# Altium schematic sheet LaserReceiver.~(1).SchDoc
size A
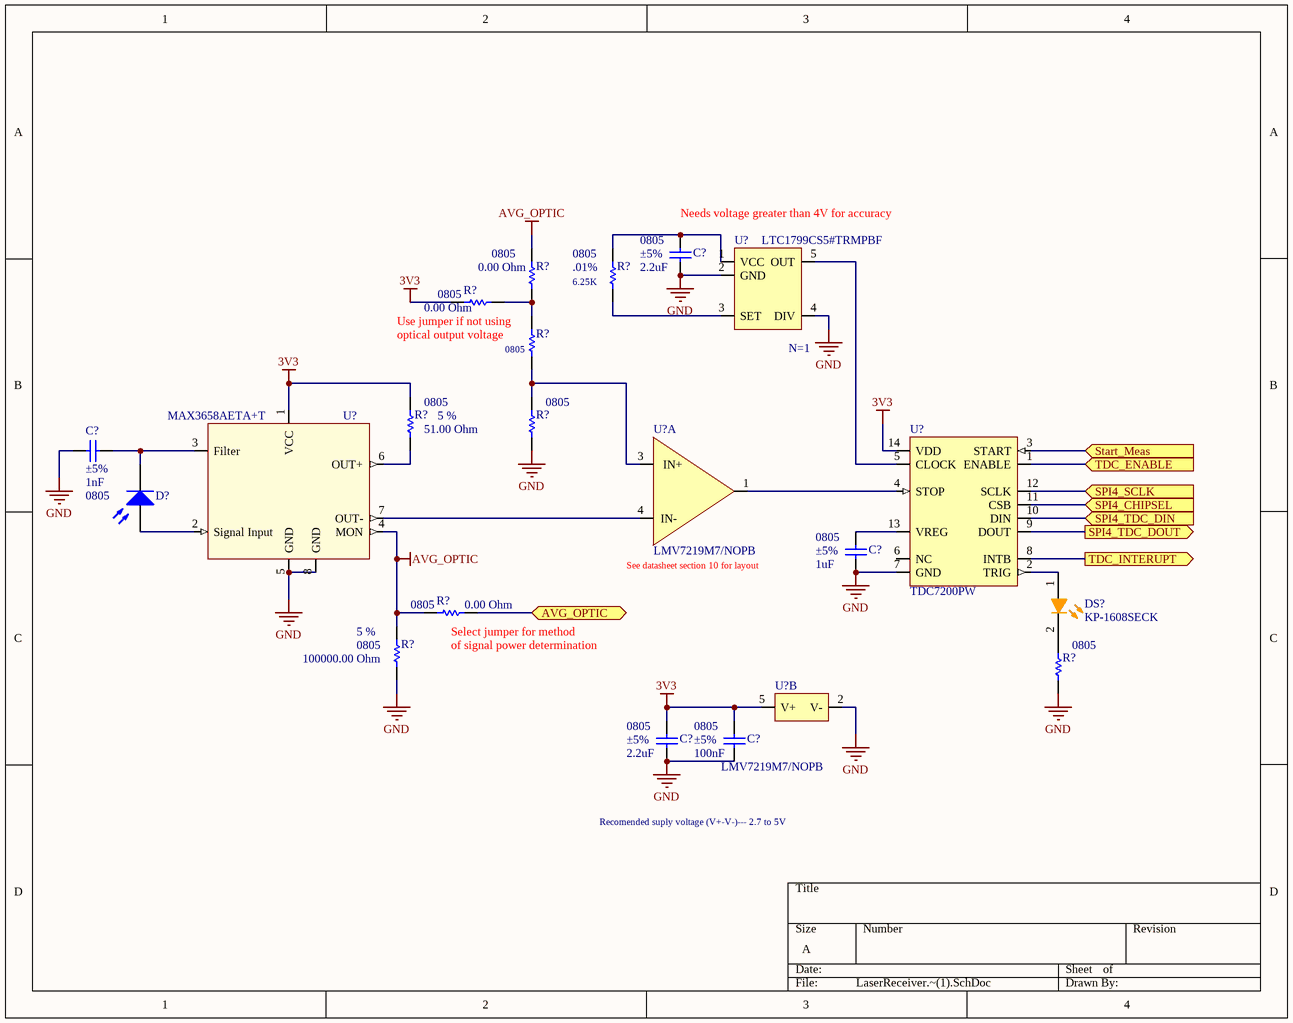
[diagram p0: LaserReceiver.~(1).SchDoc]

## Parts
(Parts that share a designator on the sheet are numbered #1, #2 ... from top to bottom, then left to right.)
C?#1  value 2.2uF  Tolerance: ±5%  Case-EIA: 0805  [CAPC0805(2012)100_M]  (hidden comment: CAP 2.2uF 6.3V 0805(2012))
C?#2  value 1nF  Tolerance: ±5%  Case-EIA: 0805  [CAPC0805(2012)100_M]  (hidden comment: CAP 1nF 6.3V 0805(2012))
C?#3  value 1uF  Tolerance: ±5%  Case-EIA: 0805  [CAPC0805(2012)100_M]  (hidden comment: CAP 1uF 6.3V 0805(2012))
C?#4  value 2.2uF  Tolerance: ±5%  Case-EIA: 0805  [CAPC0805(2012)100_M]  (hidden comment: CAP 2.2uF 6.3V 0805(2012))
C?#5  value 100nF  Tolerance: ±5%  Case-EIA: 0805  [CAPC0805(2012)100_M]  (hidden comment: CAP 100nF 6.3V 0805(2012))
D?  Photo Sen  [PIN2]  (value not drawn)
DS?  KP-1608SECK  [KING-0603LED_ORANGE_V]
R?#1  value 0.00 Ohm  Case-EIA: 0805  [RESC0805(2012)_N]  (hidden comment: Jumper 0805(2012))
R?#2  value 0.00 Ohm  Case-EIA: 0805  [RESC0805(2012)_N]  (hidden comment: Jumper 0805(2012))
R?#3  value 6.25K  Tolerance: .01%  Case-EIA: 0805  [RESC0805(2012)_N]  (hidden comment: 6.25k 5% 0805(2012))
R?#4  Case-EIA: 0805  [RESC0805(2012)_N]  (hidden comment: 51R 5% 0805(2012))
R?#5  value 51.00 Ohm  Tolerance: 5 %  Case-EIA: 0805  [RESC0805(2012)_N]  (hidden comment: 51R 5% 0805(2012))
R?#6  Case-EIA: 0805  [RESC0805(2012)_N]  (hidden comment: 51R 5% 0805(2012))
R?#7  value 0.00 Ohm  Case-EIA: 0805  [RESC0805(2012)_N]  (hidden comment: Jumper 0805(2012))
R?#8  value 100000.00 Ohm  Tolerance: 5 %  Case-EIA: 0805  [RESC0805(2012)_L]  (hidden comment: 100K 5% 0805(2012))
R?#9  Case-EIA: 0805  [RESC0805(2012)_N]  (hidden comment: 51R 5% 0805(2012))
U?#1  LTC1799CS5#TRMPBF
U?#2  MAX3658AETA+T
U?#3  LMV7219M7/NOPB  (part A of 2)
U?#4  TDC7200PW
U?#5  LMV7219M7/NOPB  (part B of 2)

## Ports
AVG_OPTIC, SPI4_CHIPSEL (in), SPI4_SCLK (in), SPI4_TDC_DIN (in), SPI4_TDC_DOUT (out), Start_Meas (in), TDC_ENABLE (in), TDC_INTERUPT (out)

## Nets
3V3: C?#4.2 C?#5.2 R?#1.1 R?#5.2 U?#2.1(VCC) U?#4.14(VDD) U?#5.5(V+)
AVG_OPTIC: R?#2.2 R?#7.1 R?#8.2 U?#2.4(MON)
GND: C?#1.1 C?#2.1 C?#3.1 C?#4.1 C?#5.1 R?#6.1 R?#8.1 R?#9.1 U?#1.2(GND) U?#1.4(DIV) U?#2.5(GND) U?#2.8(GND) U?#2.9(PAD) U?#4.7(GND) U?#5.2(V-)
AVG_OPTIC: R?#7.2 ; port AVG_OPTIC  [a separate net that carries the same name]
SPI4_CHIPSEL: U?#4.11(CSB) ; port SPI4_CHIPSEL
SPI4_SCLK: U?#4.12(SCLK) ; port SPI4_SCLK
SPI4_TDC_DIN: U?#4.10(DIN) ; port SPI4_TDC_DIN
SPI4_TDC_DOUT: U?#4.9(DOUT) ; port SPI4_TDC_DOUT
Start_Meas: U?#4.3(START) ; port Start_Meas
TDC_ENABLE: U?#4.1(ENABLE) ; port TDC_ENABLE
TDC_INTERUPT: U?#4.8(INTB) ; port TDC_INTERUPT
NetC?#1_2: C?#1.2 R?#3.2 U?#1.1(VCC)
NetC?#2_2: C?#2.2 D?.2(K) U?#2.3(Filter)
NetC?#3_2: C?#3.2 U?#4.13(VREG)
NetD?_1: D?.1(A) U?#2.2(Signal_Input)
NetDS?_1: DS?.1(A) U?#4.2(TRIG)
NetDS?_2: DS?.2(K) R?#9.2
NetR?#1_2: R?#1.2 R?#2.1 R?#4.2
NetR?#3_1: R?#3.1 U?#1.3(SET)
NetR?#4_1: R?#4.1 R?#6.2 U?#3.3(IN+)
NetR?#5_1: R?#5.1 U?#2.6(OUT+)
NetU?#1_5: U?#1.5(OUT) U?#4.5(CLOCK)
NetU?#2_7: U?#2.7(OUT-) U?#3.4(IN-)
NetU?#3_1: U?#3.1(OUT) U?#4.4(STOP)

Not connected (* = marked no-connect by the designer): U?#4 6(NC)

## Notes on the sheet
- Needs voltage greater than 4V for accuracy
- (near R?#4) Use jumper if not using
- (near R?#4) optical output voltage
- (near U?#1) N=1
- See datasheet section 10 for layout
- (near R?#7) Select jumper for method
- (near R?#7) of signal power determination
- Recomended suply voltage (V+-V-)--- 2.7 to 5V

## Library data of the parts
C?#1 C?#4 = CMP-1036-02947-1: CAP 2.2unF 6.3V ±5% 0805 (2012 Metric) Thickness 1mm SMD; Case-Metric: 2012
C?#2 = CMP-1036-02947-1: CAP 1nF 6.3V ±5% 0805 (2012 Metric) Thickness 1mm SMD; Case-Metric: 2012
C?#3 = CMP-1036-02947-1: CAP 1uF 6.3V ±5% 0805 (2012 Metric) Thickness 1mm SMD; Case-Metric: 2012
C?#5 = CMP-1036-02947-1: CAP 100nF 6.3V ±5% 0805 (2012 Metric) Thickness 1mm SMD; Case-Metric: 2012
D? = Photo Sen: Photosensitive Diode
DS? = CMP-0404-00002-1: LED, SMT, 0603(1608), 1.1mm thickness, Orange; Manufacturer: Kingbright; Power Dissipation: 75 mW; Packing Type: 2000 pcs / reel; Reverse Voltage: 5 V; Forward Current: 30 mA
R?#1 R?#2 R?#7 = CMP-1013-00001-1: Jumper 0805 (2012 Metric); Tolerance: None; Case-Metric: 2012
R?#3 = CMP-1013-00043-1: 6.25k 0.125W 5% 0805 (2012 Metric)  SMD; Case-Metric: 2012
R?#4 R?#6 R?#9 = CMP-1013-00043-1: 51R 0.125W 5% 0805 (2012 Metric)  SMD; Value: 51.00 Ohm; Case-Metric: 2012
R?#5 = CMP-1013-00043-1: 51R 0.125W 5% 0805 (2012 Metric)  SMD; Case-Metric: 2012
R?#8 = CMP-1013-00122-1: 100K 0.125W 5% 0805 (2012 Metric)  SMD; Case-Metric: 2012
U?#1 = LTC1799CS5#TRMPBF: IC OSC SILICON PROG TSOT23-5
U?#2 = MAX3658AETA+T: IC AMP TRANSIMPEDANCE 8-TDFN
U?#3 U?#5 = LMV7219M7/NOPB: IC COMPARATOR SC-70-5
U?#4 = TDC7200PW: STATIC ULTRASONIC FLOWMETER AF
